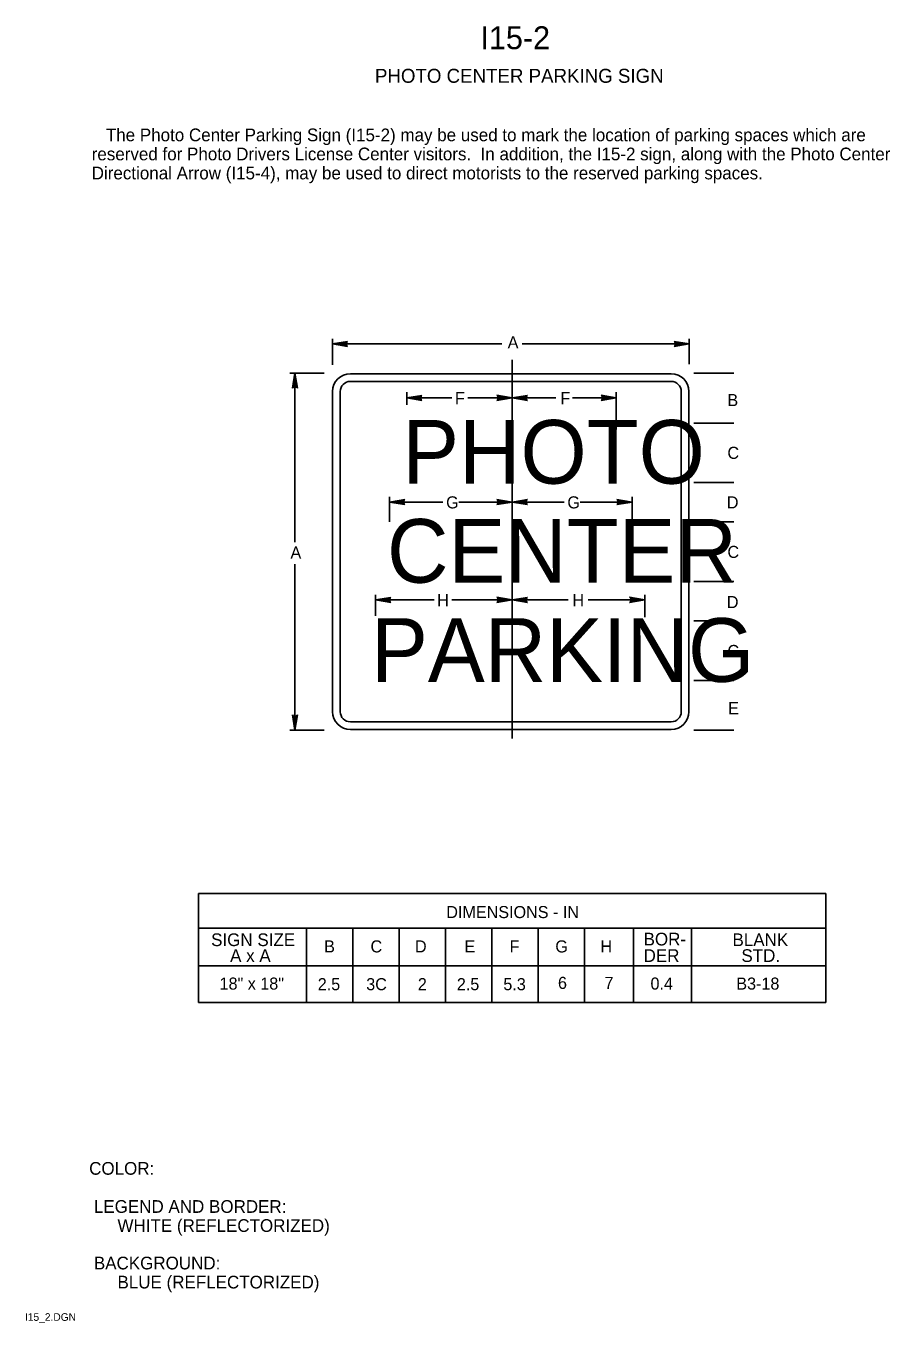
# Model space of a CAD drawing. Extents: x 0.013 to 0.183, y 0.004 to 0.259.
import ezdxf

# ---------------------------------------------------------------- set-up
doc = ezdxf.new("R2010")
doc.units = 0
for name, color, linetype in [('1', 7, 'Continuous'), ('2', 7, 'Continuous'), ('3', 7, 'Continuous')]:
    doc.layers.add(name, color=color, linetype=linetype)

# ---------------------------------------------------------------- blocks, each defined once
blk = doc.blocks.new('RARROW')
at = {"layer": '3'}
for p, q in [((-2.156, 0.285), (-2.2665, 0.384625)), ((-2.2665, 0.384625), (0, 0)), ((0, 0), (-2.2665, -0.379125)), ((-2.156, 0.285), (-2.075625, 0.12075)), ((0, 0), (-2.156, 0.285)), ((-2.14975, -0.2705), (0, 0)), ((-2.075625, 0.12075), (0, 0)), ((0, 0), (-2.074, -0.108)), ((-2.2665, -0.379125), (-2.14975, -0.2705)), ((-2.074, -0.108), (-2.14975, -0.2705))]:
    blk.add_line(p, q, dxfattribs=at)

msp = doc.modelspace()

# ---------------------------------------------------------------- linework, layer by layer
at = {"layer": '1'}
msp.add_line((0.10837, 0.1935), (0.10837, 0.119), dxfattribs=at)
at = {"layer": '3'}
for p, q in [((0.073, 0.1925), (0.073, 0.19762)), ((0.10637, 0.19662), (0.073, 0.19662)), ((0.11038, 0.19662), (0.14325, 0.19662)), ((0.14325, 0.19262), (0.14325, 0.19762)), ((0.07138, 0.19088), (0.06463, 0.19088)), ((0.06563, 0.15763), (0.06563, 0.19088)), ((0.07654, 0.19075), (0.13967, 0.19075)), ((0.07654, 0.18925), (0.13967, 0.18925)), ((0.14413, 0.19088), (0.152, 0.19088)), ((0.07304, 0.12425), (0.07304, 0.18725)), ((0.07454, 0.12425), (0.07454, 0.18725)), ((0.08763, 0.18463), (0.08763, 0.18713)), ((0.10837, 0.18575), (0.10837, 0.18713)), ((0.12887, 0.17975), (0.12887, 0.18713)), ((0.14167, 0.18725), (0.14167, 0.12425)), ((0.14317, 0.18725), (0.14317, 0.12425)), ((0.0965, 0.186), (0.08763, 0.186)), ((0.09963, 0.186), (0.10837, 0.186)), ((0.117, 0.186), (0.10837, 0.186)), ((0.12025, 0.186), (0.12887, 0.186)), ((0.14413, 0.181), (0.152, 0.181)), ((0.14413, 0.16937), (0.152, 0.16937)), ((0.08425, 0.16162), (0.08425, 0.1665)), ((0.10837, 0.1655), (0.10837, 0.1665)), ((0.132, 0.16175), (0.132, 0.1665)), ((0.09475, 0.1655), (0.08425, 0.1655)), ((0.09788, 0.1655), (0.10837, 0.1655)), ((0.11863, 0.1655), (0.10837, 0.1655)), ((0.12175, 0.1655), (0.132, 0.1655)), ((0.14413, 0.16162), (0.152, 0.16162)), ((0.06563, 0.15325), (0.06563, 0.12062)), ((0.14413, 0.14988), (0.152, 0.14988)), ((0.0815, 0.14313), (0.0815, 0.14725)), ((0.093, 0.14625), (0.0815, 0.14625)), ((0.0965, 0.14625), (0.10837, 0.14625)), ((0.10837, 0.144), (0.10837, 0.14725)), ((0.11938, 0.14625), (0.10837, 0.14625)), ((0.12337, 0.14625), (0.1345, 0.14625)), ((0.1345, 0.14288), (0.1345, 0.14725)), ((0.14413, 0.14213), (0.152, 0.14213)), ((0.14413, 0.13037), (0.152, 0.13037)), ((0.07138, 0.12062), (0.06463, 0.12062)), ((0.13967, 0.12225), (0.07654, 0.12225)), ((0.13967, 0.12075), (0.07654, 0.12075)), ((0.14413, 0.12062), (0.152, 0.12062)), ((0.04662, 0.0885), (0.17012, 0.0885)), ((0.04662, 0.0885), (0.04662, 0.067)), ((0.17012, 0.0885), (0.17012, 0.067)), ((0.17012, 0.08163), (0.04662, 0.08163)), ((0.06792, 0.08162), (0.06792, 0.067)), ((0.077, 0.08163), (0.077, 0.067)), ((0.08613, 0.08163), (0.08613, 0.067)), ((0.09525, 0.08163), (0.09525, 0.067)), ((0.10437, 0.08163), (0.10437, 0.067)), ((0.1135, 0.08163), (0.1135, 0.067)), ((0.12262, 0.08163), (0.12262, 0.067)), ((0.13229, 0.08162), (0.13229, 0.067)), ((0.14367, 0.08162), (0.14367, 0.067)), ((0.17012, 0.07425), (0.04662, 0.07425)), ((0.17012, 0.067), (0.04662, 0.067))]:
    msp.add_line(p, q, dxfattribs=at)
for centre, radius, start, end in [((0.07654, 0.18725), 0.0035, 90, 180), ((0.07654, 0.18725), 0.002, 90, 180), ((0.13967, 0.18725), 0.0035, 0, 90), ((0.13967, 0.18725), 0.002, 0, 90), ((0.07654, 0.12425), 0.0035, 180, 270), ((0.07654, 0.12425), 0.002, 180, 270), ((0.13967, 0.12425), 0.002, 270, 0), ((0.13967, 0.12425), 0.0035, 270, 0)]:
    msp.add_arc(centre, radius, start, end, dxfattribs=at)

# ---------------------------------------------------------------- block references
at = {"layer": '3', "xscale": 0.0013236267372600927, "yscale": 0.001309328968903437}
for p, rotation in [((0.073, 0.19662), 180), ((0.06563, 0.19088), 90), ((0.08763, 0.186), 180), ((0.10837, 0.186), 180), ((0.08425, 0.1655), 180), ((0.10837, 0.1655), 180), ((0.0815, 0.14625), 180), ((0.10837, 0.14625), 180), ((0.06563, 0.12062), -90)]:
    msp.add_blockref('RARROW', p, dxfattribs=dict(at, rotation=rotation))
for p in [(0.14325, 0.19662), (0.10837, 0.186), (0.12887, 0.186), (0.10837, 0.1655), (0.132, 0.1655), (0.10837, 0.14625), (0.1345, 0.14625)]:
    msp.add_blockref('RARROW', p, dxfattribs=at)

# ---------------------------------------------------------------- texts
at = {"layer": '1'}
for s, height, p in [('I15-2', 0.0045, (0.10213, 0.25462)), ('PHOTO CENTER PARKING SIGN', 0.0027503, (0.08138, 0.248)), ('PHOTO', 0.012527, (0.08675, 0.16912)), ('CENTER', 0.012527, (0.08375, 0.14963)), ('PARKING', 0.012527, (0.08063, 0.13012)), ('COLOR:', 0.0025, (0.02513, 0.03313)), (' LEGEND AND BORDER:', 0.0024998, (0.02513, 0.02563)), ('      WHITE (REFLECTORIZED)', 0.0024998, (0.02513, 0.02188)), (' BACKGROUND:', 0.0024998, (0.02513, 0.0145)), ('      BLUE (REFLECTORIZED)', 0.0024998, (0.02513, 0.01075)), ('I15_2.DGN', 0.0015, (0.0125, 0.00438))]:
    msp.add_text(s, height=height, dxfattribs=at).set_placement(p)
at = {"layer": '2'}
for s, height, p in [('   The Photo Center Parking Sign (I15-2) may be used to mark the location of parking spaces which are', 0.00249975, (0.02563, 0.2365)), ('reserved for Photo Drivers License Center visitors.  In addition, the I15-2 sign, along with the Photo Center', 0.00249975, (0.02563, 0.23275)), ('Directional Arrow (I15-4), may be used to direct motorists to the reserved parking spaces.', 0.0024998, (0.02563, 0.229))]:
    msp.add_text(s, height=height, dxfattribs=at).set_placement(p)
at = {"layer": '3'}
for s, height, p in [('A', 0.00238, (0.1075, 0.19575)), ('F', 0.00238, (0.09713, 0.18475)), ('F', 0.00238, (0.11788, 0.18475)), ('B', 0.00238, (0.15075, 0.18438)), ('C', 0.00238, (0.15075, 0.174)), ('G', 0.00238, (0.09538, 0.16425)), ('G', 0.00238, (0.11925, 0.16425)), ('D', 0.00238, (0.15063, 0.16425)), ('A', 0.00238, (0.06475, 0.15438)), ('C', 0.00238, (0.15075, 0.1545)), ('H', 0.00238, (0.09362, 0.145)), ('H', 0.00238, (0.12025, 0.145)), ('D', 0.00238, (0.15063, 0.14463)), ('C', 0.00238, (0.15075, 0.135)), ('E', 0.00238, (0.15088, 0.12375)), ('DIMENSIONS - IN', 0.0023752, (0.09542, 0.08363)), ('SIGN SIZE', 0.0025, (0.04913, 0.07812)), ('B', 0.00238, (0.07138, 0.07687)), ('C', 0.00238, (0.0805, 0.07687)), ('D', 0.00238, (0.08925, 0.07687)), ('E', 0.00238, (0.099, 0.07687)), ('F', 0.00238, (0.10787, 0.07687)), ('G', 0.00238, (0.11688, 0.07687)), ('H', 0.00238, (0.12575, 0.07687)), ('BOR-', 0.0025, (0.13425, 0.07825)), ('BLANK', 0.0025, (0.15175, 0.07812)), ('A x A', 0.0025, (0.05287, 0.075)), ('DER', 0.0025, (0.13425, 0.075)), ('STD.', 0.0025, (0.1535, 0.075)), ('18" x 18"', 0.002375, (0.0508, 0.06956)), ('2.5', 0.002375, (0.07012, 0.06944)), ('3C', 0.002375, (0.07966, 0.06944)), ('2', 0.00238, (0.08982, 0.06944)), ('2.5', 0.002375, (0.0975, 0.06944)), ('5.3', 0.002375, (0.10665, 0.06944)), ('6', 0.00238, (0.1174, 0.06969)), ('7', 0.00238, (0.12656, 0.06969)), ('0.4', 0.002375, (0.13561, 0.06956)), ('B3-18', 0.002375, (0.1525, 0.06956))]:
    msp.add_text(s, height=height, dxfattribs=at).set_placement(p)

doc.saveas('drawing.dxf')
